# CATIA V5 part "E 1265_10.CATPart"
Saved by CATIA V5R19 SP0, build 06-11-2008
Nomenclature: E 1265_10
Description: PART-E 1265_10-DESC
Property "Hersteller": "Meusburger"
Property "Material": "INOX 1.4305"
Property "Bestellnummer": "E 1265/10"
Property "Teilenummer": "E 1265/10"
Property "Beschreibung": "Druckstück gefedert zum Einpressen _ Spring-loaded thrust piece to be pressed in"
Material "Steel": density 7860 kg/m3, Young's modulus 2e+11 Pa, Poisson ratio 0.266, thermal expansion 1.17e-05 1/K
Bounding box of the stored display mesh (mm): x -5.5 to 5.5, y -5.491 to 5.491, z -13 to 3.3
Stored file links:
  G:\UTB\Kombinované\Bakalářská práce\Catia\FORMA\E 1265_10.CATPart
  D:\Aplikace\CATIA\Nová složka\win_b64\startup\materials\Catalog.CATMaterial
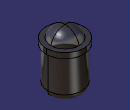
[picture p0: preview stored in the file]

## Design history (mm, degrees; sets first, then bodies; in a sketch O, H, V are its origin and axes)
Body1 "E 1265_10" (main body)
  Solid1: solid without history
